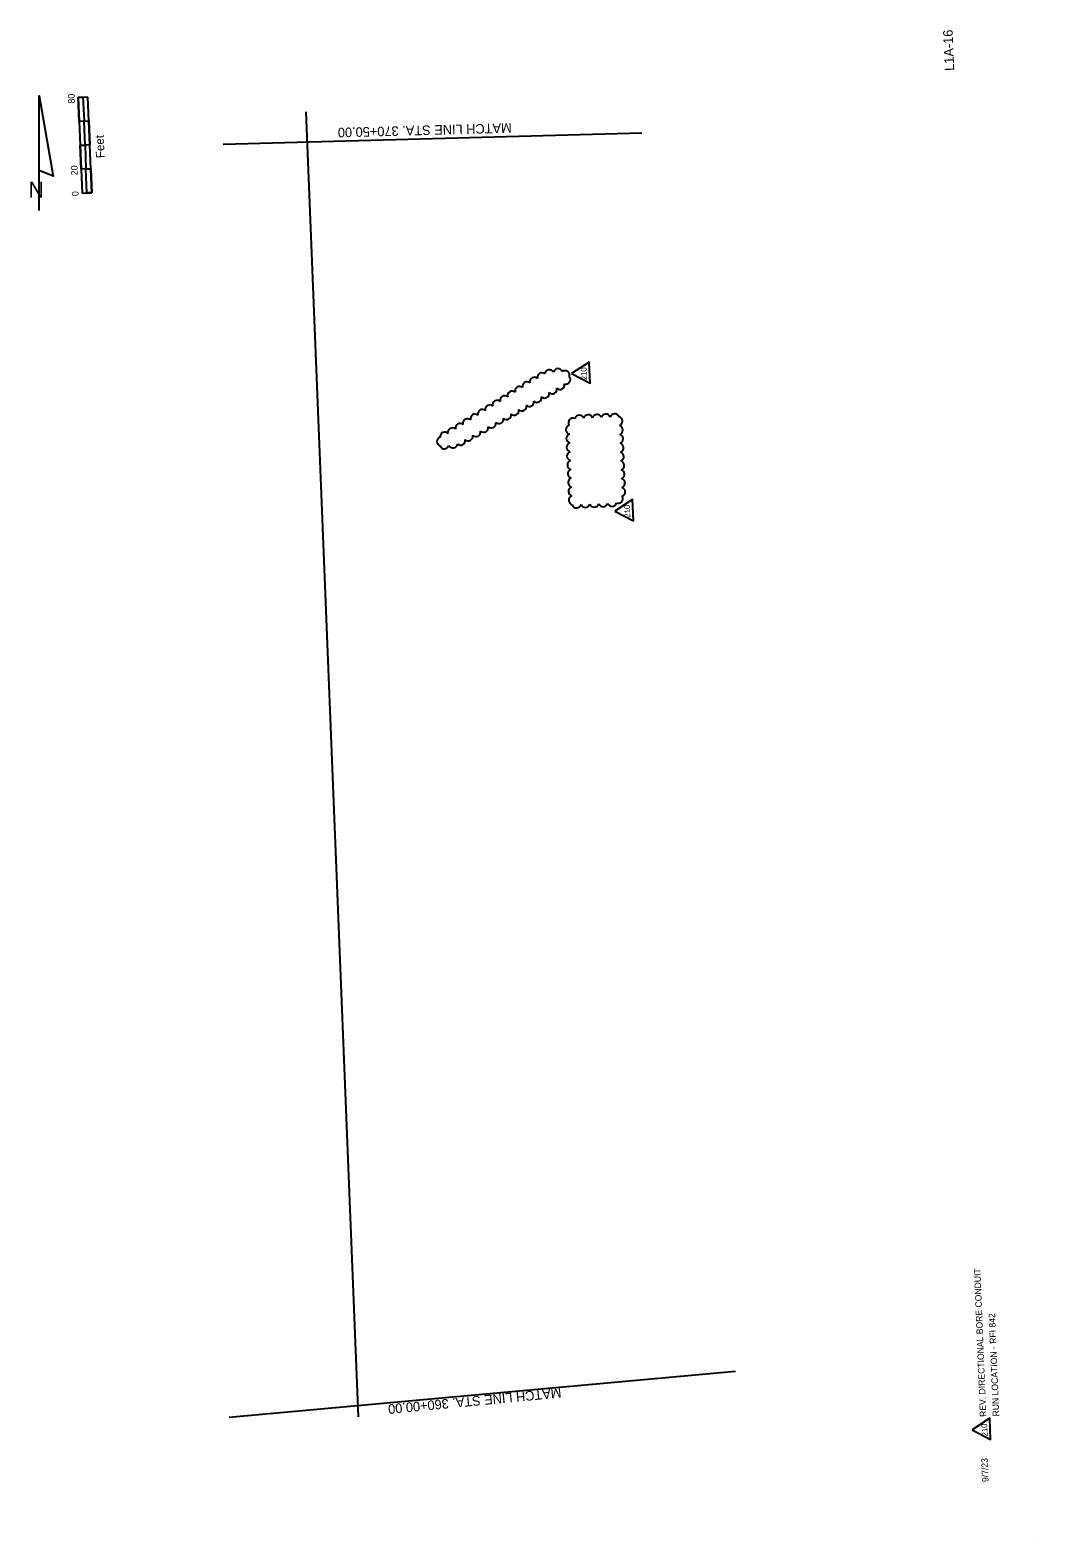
# Model space of a CAD drawing. Extents: x 929307 to 930150, y 612199 to 613459.
import ezdxf

# ---------------------------------------------------------------- set-up
doc = ezdxf.new("R2010")
doc.units = 0
for name, color, linetype in [('ActivePointCell_dp', 7, 'Continuous'), ('AdhocPoint_dp', 7, 'Continuous'), ('ConduitDB', 7, 'Continuous'), ('MatchLines_dp', 7, 'Continuous'), ('NorthArw_dp', 7, 'Continuous'), ('PoleElec_ep', 7, 'Continuous'), ('PullBox', 7, 'Continuous'), ('TextMisc', 7, 'Continuous')]:
    doc.layers.add(name, color=color, linetype=linetype)

msp = doc.modelspace()

# ---------------------------------------------------------------- linework, layer by layer
at = {"layer": 'ConduitDB'}
for points in [[(929759.9, 613171.5), (929775.3, 613163.5), (929774.6, 613181.1)], [(929796.1, 613056.6), (929811.5, 613048.6), (929810.8, 613066.2)], [(930094.8, 612288.9), (930110.1, 612280.9), (930109.4, 612298.5)]]:
    msp.add_lwpolyline(points, close=True, dxfattribs=at)
for centre, radius, start, end in [((929741.4, 613170.9), 3.84, 28.5651, 173.5651), ((929748.5, 613171.8), 3.84, 20.6502, 165.6502), ((929722.6, 613160.8), 3.84, 49.2093, 194.2093), ((929728.9, 613164.6), 3.84, 49.2093, 194.2093), ((929735.1, 613168.4), 3.84, 49.2093, 194.2093), ((929750.2, 613162.1), 3.84, 226.7265, 11.7265), ((929754.4, 613170.1), 3.83, 342.0124, 127.0124), ((929755, 613166.5), 3.84, 253.5546, 38.5546), ((929697.7, 613145.4), 3.84, 49.2093, 194.2093), ((929704, 613149.2), 3.84, 49.2093, 194.2093), ((929710.2, 613153.1), 3.84, 49.2093, 194.2093), ((929716.4, 613156.9), 3.84, 49.2093, 194.2093), ((929731, 613151.3), 3.84, 226.7265, 11.7265), ((929737.4, 613154.9), 3.84, 226.7265, 11.7265), ((929743.8, 613158.5), 3.84, 226.7265, 11.7265), ((929679.1, 613133.8), 3.84, 49.2093, 194.2093), ((929685.3, 613137.7), 3.84, 49.2093, 194.2093), ((929691.5, 613141.5), 3.84, 49.2093, 194.2093), ((929705.5, 613137), 3.84, 226.7265, 11.7265), ((929711.9, 613140.6), 3.84, 226.7265, 11.7265), ((929718.3, 613144.2), 3.84, 226.7265, 11.7265), ((929724.6, 613147.8), 3.84, 226.7265, 11.7265), ((929766.4, 613132.9), 3.88, 19.8072, 164.8072), ((929773.7, 613133.2), 3.88, 19.8072, 164.8072), ((929781.1, 613133.5), 3.88, 19.8072, 164.8072), ((929788.5, 613133.8), 3.88, 19.8072, 164.8072), ((929795.9, 613134.1), 3.88, 19.8072, 164.8072), ((929660.4, 613122.3), 3.84, 49.2093, 194.2093), ((929666.6, 613126.1), 3.84, 49.2093, 194.2093), ((929672.8, 613130), 3.84, 49.2093, 194.2093), ((929686.3, 613126.3), 3.84, 226.7265, 11.7265), ((929692.7, 613129.9), 3.84, 226.7265, 11.7265), ((929699.1, 613133.5), 3.84, 226.7265, 11.7265), ((929759, 613124.8), 3.88, 109.8072, 254.8072), ((929761, 613130.4), 3.87, 65.8871, 210.8871), ((929798.5, 613131.7), 3.88, 289.8072, 74.8072), ((929798.8, 613124.3), 3.88, 289.8072, 74.8072), ((929651.1, 613114.8), 3.84, 108.2571, 253.2571), ((929653.8, 613118.8), 3.84, 40.9648, 185.9648), ((929653.6, 613112.4), 3.84, 199.8072, 344.8072), ((929660.7, 613113.2), 3.84, 208.5587, 353.5587), ((929667.2, 613115.6), 3.84, 226.7265, 11.7265), ((929673.5, 613119.2), 3.84, 226.7265, 11.7265), ((929679.9, 613122.7), 3.84, 226.7265, 11.7265), ((929759.3, 613117.4), 3.88, 109.8072, 254.8072), ((929759.6, 613110), 3.88, 109.8072, 254.8072), ((929799.1, 613116.9), 3.88, 289.8072, 74.8072), ((929799.4, 613109.5), 3.88, 289.8072, 74.8072), ((929759.9, 613102.6), 3.88, 109.8072, 254.8072), ((929760.2, 613095.2), 3.88, 109.8072, 254.8072), ((929799.7, 613102.1), 3.88, 289.8072, 74.8072), ((929800, 613094.8), 3.88, 289.8072, 74.8072), ((929760.5, 613087.8), 3.88, 109.8072, 254.8072), ((929800.3, 613087.4), 3.88, 289.8072, 74.8072), ((929760.8, 613080.4), 3.88, 109.8072, 254.8072), ((929761.1, 613073.1), 3.88, 109.8072, 254.8072), ((929800.6, 613080), 3.88, 289.8072, 74.8072), ((929800.9, 613072.6), 3.88, 289.8072, 74.8072), ((929761.4, 613065.7), 3.88, 109.8072, 254.8072), ((929764, 613063.2), 3.88, 199.8072, 344.8072), ((929771.4, 613063.5), 3.88, 199.8072, 344.8072), ((929778.8, 613063.8), 3.88, 199.8072, 344.8072), ((929786.2, 613064.1), 3.88, 199.8072, 344.8072), ((929793.6, 613064.4), 3.88, 199.8072, 344.8072), ((929798.9, 613067), 3.87, 245.8871, 30.8871)]:
    msp.add_arc(centre, radius, start, end, dxfattribs=at)
at = {"layer": 'MatchLines_dp'}
msp.add_line((929315, 613307.7), (929315, 613403.7), dxfattribs=at)
msp.add_lwpolyline([(929315, 613341.3), (929315, 613403.7), (929326.5, 613336.5)], close=True, dxfattribs=at)
at = {"layer": 'NorthArw_dp'}
for p, q in [((929818.5, 613372.3), (929468.6, 613362.9)), ((929896.8, 612337.7), (929473.8, 612299.2))]:
    msp.add_line(p, q, dxfattribs=at)
at = {"layer": 'PoleElec_ep'}
msp.add_line((930149.6, 612198.6), (930149.6, 612198.6), dxfattribs=at)
at = {"layer": 'PullBox'}
msp.add_line((929581.9, 612299.7), (929537.9, 613390.3), dxfattribs=at)
at = {"layer": 'TextMisc'}
for p, q in [((929355.5, 613402.6), (929347.5, 613402.3)), ((929347.5, 613402.3), (929350.8, 613322.4)), ((929358.8, 613322.7), (929355.5, 613402.6)), ((929350.8, 613322.4), (929358.8, 613322.7))]:
    msp.add_line(p, q, dxfattribs=at)
for points in [[(929352.4, 613382.5), (929348.4, 613382.3), (929347.5, 613402.3), (929351.5, 613402.5)], [(929357.2, 613362.7), (929353.2, 613362.5), (929352.4, 613382.5), (929356.4, 613382.6)], [(929354, 613342.5), (929350, 613342.4), (929349.2, 613362.3), (929353.2, 613362.5)], [(929358.8, 613322.7), (929354.8, 613322.5), (929354, 613342.5), (929358, 613342.7)]]:
    msp.add_lwpolyline(points, close=True, dxfattribs=at)

# ---------------------------------------------------------------- texts
at = {"layer": 'ActivePointCell_dp'}
msp.add_text('L1A-16', height=8, rotation=92.3072, dxfattribs=at).set_placement((930079.7, 613424.6))
at = {"layer": 'AdhocPoint_dp'}
for s, height, p in [('REV. DIRECTIONAL BORE CONDUIT ', 5.376, (930106.5, 612299.8)), ('RUN LOCATION - RFI 842', 5.376, (930117.3, 612300.2)), ('9/7/23', 5.38, (930108.4, 612245.4))]:
    msp.add_text(s, height=height, rotation=92.3072, dxfattribs=at).set_placement(p)
at = {"layer": 'ConduitDB'}
for p in [(929772.8, 613166.1), (929809, 613051.2), (930107.6, 612283.5)]:
    msp.add_text('210', height=4.8, rotation=92.3072, dxfattribs=at).set_placement(p)
at = {"layer": 'MatchLines_dp'}
msp.add_text('N', height=13.4, dxfattribs=at).set_placement((929305.9, 613318.6))
at = {"layer": 'NorthArw_dp'}
for s, rotation, p in [('MATCH LINE STA. 370+50.00', 181.5416, (929709.7, 613380.8)), ('MATCH LINE STA. 360+00.00', 185.4731, (929750.9, 612323.9))]:
    msp.add_text(s, height=8, rotation=rotation, dxfattribs=at).set_placement(p)
at = {"layer": 'TextMisc'}
for s, height, p in [('80', 5.6, (929344.8, 613397.2)), ('Feet', 7.2, (929369.6, 613351.7)), ('20', 5.6, (929347.2, 613337.3)), ('0', 5.6, (929347.9, 613319.9))]:
    msp.add_text(s, height=height, rotation=92.3483, dxfattribs=at).set_placement(p)

doc.saveas('drawing.dxf')
